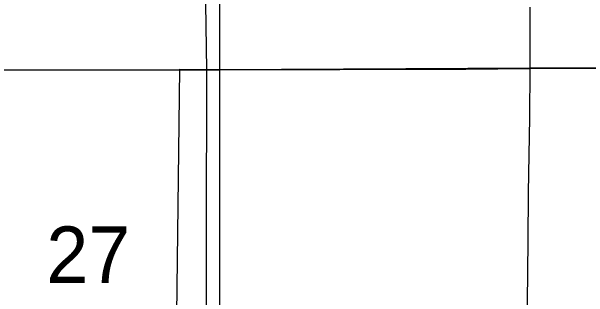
# Model space of a CAD drawing. Extents: x -38.1 to 35.9, y -2.7 to 28.5.
# Drawn here: x 8.6114 to 9.0391, y 19.2142 to 19.4259 of the extents above; entities that cross this region are included whole.
import ezdxf

# ---------------------------------------------------------------- set-up
doc = ezdxf.new("R2010")
doc.units = 0
for name, color, linetype in [('GM_X_City_Street', 7, 'Continuous'), ('GM_X_City_Street_Text', 7, 'Continuous'), ('GM_X_Corporation_Text', 7, 'Continuous'), ('GM_X_Major_River_Text', 7, 'Continuous'), ('GM_X_Minor_River', 7, 'Continuous'), ('GM_X_US_Route', 7, 'Continuous')]:
    doc.layers.add(name, color=color, linetype=linetype)

msp = doc.modelspace()

# ---------------------------------------------------------------- linework, layer by layer
at = {"layer": 'GM_X_City_Street'}
msp.add_lwpolyline([(8.99583, 19.38369), (8.99584, 19.38772), (8.99596, 19.42435), (8.9958, 19.42914)], dxfattribs=at)
at = {"layer": 'GM_X_City_Street_Text'}
msp.add_line((8.99583, 19.38369), (9.04797, 19.38403), dxfattribs=at)
for points in [[(8.54904, 19.38284), (8.60145, 19.38278), (8.64928, 19.38276), (8.73648, 19.38278)], [(8.73648, 19.38278), (8.74057, 19.38278), (8.75615, 19.38284), (8.76591, 19.38288), (8.78839, 19.38296), (8.85481, 19.38291), (8.94809, 19.38337), (8.99583, 19.38369)]]:
    msp.add_lwpolyline(points, dxfattribs=at)
at = {"layer": 'GM_X_Corporation_Text'}
for points in [[(8.75662, 17.87022), (8.75643, 17.88824), (8.75662, 18.21378), (8.75643, 18.31226), (8.75632, 18.37295), (8.75646, 18.49523), (8.75602, 18.6507), (8.75603, 18.87006), (8.75603, 18.8775), (8.756, 19.07265), (8.75602, 19.26157), (8.75614, 19.38131), (8.75615, 19.38284), (8.75556, 19.43185), (8.75552, 19.48342), (8.75567, 19.60683), (8.75582, 19.73076)], [(8.76591, 19.38346), (8.76591, 19.3844), (8.76591, 19.5174), (8.76572, 19.67833), (8.76572, 19.73076)], [(8.76644, 17.87011), (8.76663, 18.01383), (8.76645, 18.24381), (8.76629, 18.31404), (8.76591, 18.48786), (8.76653, 18.69531), (8.76645, 18.86033), (8.76639, 18.87754), (8.76591, 19.01962), (8.76591, 19.27718), (8.76591, 19.38252), (8.76591, 19.38346)]]:
    msp.add_lwpolyline(points, dxfattribs=at)
at = {"layer": 'GM_X_Major_River_Text'}
msp.add_lwpolyline([(8.9936, 19.16733), (8.99383, 19.21058), (8.99449, 19.25595), (8.99478, 19.2917), (8.99523, 19.31982), (8.99556, 19.3472), (8.99583, 19.38369)], dxfattribs=at)
at = {"layer": 'GM_X_US_Route'}
msp.add_lwpolyline([(8.60916, 18.8776), (8.61963, 18.87753), (8.62536, 18.87751), (8.63213, 18.87752), (8.65801, 18.87756), (8.6966, 18.87771), (8.73008, 18.87796), (8.73625, 19.38331), (8.76568, 19.38306), (8.99559, 19.38423), (9.04773, 19.38457), (9.0452, 19.21923), (9.23248, 19.21631), (9.23157, 19.16503), (9.23086, 18.99668), (9.42972, 18.99674)], dxfattribs=at)

# ---------------------------------------------------------------- texts
at = {"layer": 'GM_X_Minor_River'}
msp.add_text('27', height=0.041856, rotation=0, dxfattribs=at).set_placement((8.63721, 19.2249))

doc.saveas('drawing.dxf')
